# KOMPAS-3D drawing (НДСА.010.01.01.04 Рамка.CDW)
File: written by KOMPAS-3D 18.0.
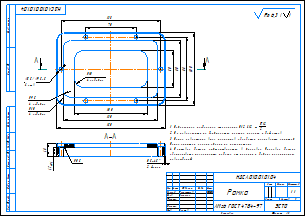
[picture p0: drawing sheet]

Sheet 1: A3, landscape

Document properties: Автор: Пользователь Windows; Параметр неуказанной шероховатости: Ra 6,3; PDM_DOCXDTO: <item xmlns="http://appius.ru/pdm" xmlns:xs="http://www.w3.org/2001/XMLSchema" xmlns:xsi="http://www.w3.org/2001/XMLSchema-instance" xsi:type="item">  <element xmlns:d2p1="http://v8.1c.ru/8.1/data/enterprise/current-config" xsi:type="d2p1:CatalogRef.aps_Элемен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; Полное имя файла: F:\Temp\НДСА.010.01.01.04 Рамка.CDW

Title block, sheet 1: Наименование: Рамка; designation: НДСА.010.01.01.04; Материал: АМг6 ГОСТ 4784-97; scale: 1:1; sheets: 1; organisation: ЭСТО; Форматы листов документа: A3; stored path: E:\paul\Новая папка (5)\Виноградов\Новая папка\столик\Новая папка (9)\НДСА.010.01.01.00 СБ Камера\НДСА.010.01.01.04 Рамка.cdw; Разработал: Горностаев; Проверил: Дзензель; Утвердил: Локтев; Разработал, date: 27.03.2018

Views: Вид 1, Спереди, Разрез А-А
Referenced files in /: 9,5x5
Referenced files in E:\paul\Новая папка (5)\Виноградов\Новая папка\столик\Новая папка (9)\НДСА.010.01.01.00 СБ Камера\: НДСА.010.01.01.04 Рамка.m3d
Referenced files in E:\ICP\НДСА.010 Технологический модуль\НДСА.010.01 Корпус\НДСА.010.01.01 Камера\: НДСА.010.01.01.04 Рамка.m3d
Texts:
  Ra 6,3
  Ra 6,3 ( )
Dimensions and other numbers on the sheet: 70; 138; 50; 80; 88; 100; 5,5; 6 отв.; 10; 4 радиуса; 9,5; 150; 130; 18; 12; 0,5; 2 фаски; 1:1; 1; 27.03.2018

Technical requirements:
  Неуказанные предельные отклонения H12, h12,    IT12 2 .
  На поверхности не допускается наличие царапин и дефектов.
  После завершения всех процессов обработки произвести очистку.
  После очистки, голыми руками не прикасаться.
  Поставка детали осуществляется в упаковке. Упаковка должна
  обеспечивать сохранность изделия от царапин и других механических
  повреждений.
